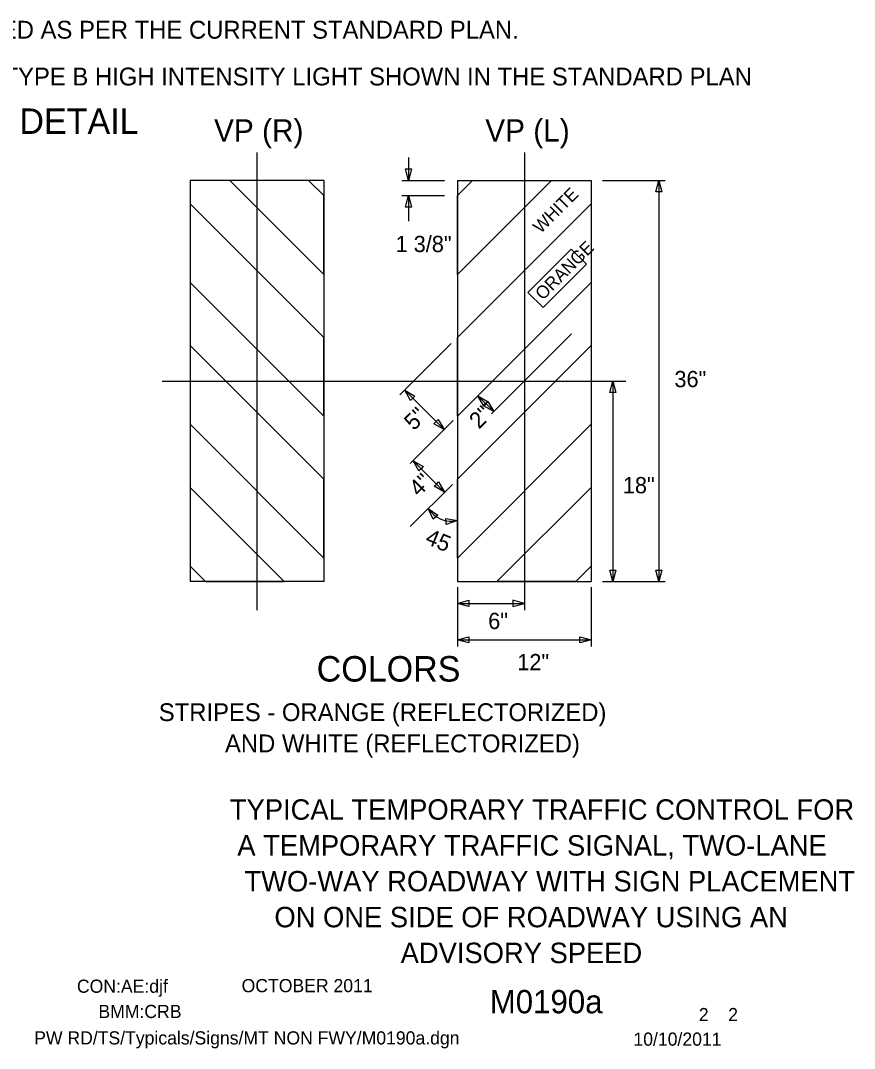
# Model space of a CAD drawing. Extents: x 16739 to 18486, y 7218 to 8208.
# Drawn here: x 18093.1 to 18486.1, y 7218.1 to 7702.3 of the extents above; entities that cross this region are included whole.
import ezdxf

# ---------------------------------------------------------------- set-up
doc = ezdxf.new("R2010")
doc.units = 0
for name, color, linetype in [('BORDER', 7, 'Continuous'), ('BORDER_SIGNAL_WO', 7, 'Continuous'), ('TRAFFIC_SIGNS_PR', 7, 'Continuous'), ('TYPICAL_TEXT_DIMEN_PR', 7, 'Continuous')]:
    doc.layers.add(name, color=color, linetype=linetype)

msp = doc.modelspace()

# ---------------------------------------------------------------- linework, layer by layer
at = {"layer": 'TRAFFIC_SIGNS_PR'}
for p, q in [((18235.99, 7627.03), (18172.99, 7627.03)), ((18172.99, 7627.03), (18172.99, 7438.03)), ((18235.99, 7582.76), (18191.73, 7627.03)), ((18235.99, 7619.89), (18228.85, 7627.03)), ((18235.99, 7627.03), (18235.99, 7438.03)), ((18299.02, 7627.03), (18362.02, 7627.03)), ((18299.02, 7627.03), (18299.02, 7438.03)), ((18299.02, 7619.89), (18306.16, 7627.03)), ((18299.02, 7582.76), (18343.29, 7627.03)), ((18362.02, 7627.03), (18362.02, 7438.03)), ((18235.99, 7553.07), (18172.99, 7616.07)), ((18299.02, 7553.07), (18362.02, 7616.07)), ((18235.99, 7515.94), (18172.99, 7578.94)), ((18299.02, 7515.94), (18362.02, 7578.94)), ((18308.3, 7562.35), (18317.58, 7571.63)), ((18235.99, 7486.25), (18172.99, 7549.25)), ((18299.02, 7486.25), (18362.02, 7549.25)), ((18235.99, 7449.12), (18172.99, 7512.12)), ((18299.02, 7449.12), (18362.02, 7512.12)), ((18217.39, 7438.03), (18172.99, 7482.42)), ((18317.63, 7438.03), (18362.02, 7482.42)), ((18180.26, 7438.03), (18172.99, 7445.3)), ((18354.75, 7438.03), (18362.02, 7445.3)), ((18235.99, 7438.03), (18172.99, 7438.03)), ((18299.02, 7438.03), (18362.02, 7438.03))]:
    msp.add_line(p, q, dxfattribs=at)
for points in [[(18228.85, 7627.03), (18191.73, 7627.03), (18235.99, 7582.76), (18235.99, 7619.89)], [(18306.16, 7627.03), (18343.29, 7627.03), (18299.02, 7582.76), (18299.02, 7619.89)], [(18235.99, 7553.07), (18172.99, 7616.07), (18172.99, 7578.94), (18235.99, 7515.94)], [(18299.02, 7553.07), (18362.02, 7616.07), (18362.02, 7578.94), (18299.02, 7515.94)], [(18235.99, 7486.25), (18172.99, 7549.25), (18172.99, 7512.12), (18235.99, 7449.12)], [(18299.02, 7486.25), (18362.02, 7549.25), (18362.02, 7512.12), (18299.02, 7449.12)], [(18172.99, 7482.42), (18172.99, 7445.3), (18180.26, 7438.03), (18217.39, 7438.03)], [(18362.02, 7482.42), (18362.02, 7445.3), (18354.75, 7438.03), (18317.63, 7438.03)]]:
    msp.add_lwpolyline(points, close=True, dxfattribs=at)
at = {"layer": 'TYPICAL_TEXT_DIMEN_PR'}
for p, q in [((18204.49, 7640.16), (18204.49, 7424.63)), ((18275.92, 7637.88), (18275.92, 7627.03)), ((18330.52, 7640.16), (18330.52, 7424.63)), ((18275.92, 7627.03), (18274.48, 7632.42)), ((18274.48, 7632.42), (18275.92, 7632.42)), ((18275.92, 7632.42), (18277.36, 7632.42)), ((18277.36, 7632.42), (18275.92, 7627.03)), ((18272.77, 7627.03), (18292.93, 7627.03)), ((18367.39, 7627.03), (18396.81, 7627.03)), ((18392.44, 7621.64), (18393.89, 7627.03)), ((18393.89, 7627.03), (18393.89, 7438.03)), ((18393.89, 7627.03), (18395.33, 7621.64)), ((18272.77, 7619.89), (18292.93, 7619.89)), ((18274.48, 7614.5), (18275.92, 7619.89)), ((18275.92, 7619.89), (18275.92, 7607.83)), ((18275.92, 7619.89), (18277.36, 7614.5)), ((18393.89, 7621.64), (18392.44, 7621.64)), ((18395.33, 7621.64), (18393.89, 7621.64)), ((18275.92, 7614.5), (18274.48, 7614.5)), ((18277.36, 7614.5), (18275.92, 7614.5)), ((18315.08, 7517.08), (18352.8, 7554.81)), ((18271.9, 7525.95), (18296.09, 7550.14)), ((18159.87, 7532.53), (18378.29, 7532.53)), ((18370.78, 7527.14), (18372.22, 7532.53)), ((18372.22, 7532.53), (18372.22, 7438.03)), ((18372.22, 7532.53), (18373.67, 7527.14)), ((18292.72, 7509.64), (18274.16, 7528.21)), ((18276.95, 7523.38), (18274.16, 7528.21)), ((18274.16, 7528.21), (18278.99, 7525.42)), ((18278.99, 7525.42), (18277.97, 7524.4)), ((18316.1, 7518.1), (18308.64, 7525.56)), ((18311.43, 7520.73), (18308.64, 7525.56)), ((18308.64, 7525.56), (18313.47, 7522.78)), ((18372.22, 7527.14), (18370.78, 7527.14)), ((18373.67, 7527.14), (18372.22, 7527.14)), ((18277.97, 7524.4), (18276.95, 7523.38)), ((18311.27, 7520.89), (18312.29, 7521.91)), ((18316.1, 7518.1), (18311.27, 7520.89)), ((18312.45, 7521.75), (18311.43, 7520.73)), ((18312.29, 7521.91), (18313.31, 7522.93)), ((18313.47, 7522.78), (18312.45, 7521.75)), ((18313.31, 7522.93), (18316.1, 7518.1)), ((18276.74, 7493.66), (18296.97, 7513.89)), ((18287.89, 7512.43), (18288.91, 7513.45)), ((18292.72, 7509.64), (18287.89, 7512.43)), ((18288.91, 7513.45), (18289.93, 7514.47)), ((18289.93, 7514.47), (18292.72, 7509.64)), ((18292.92, 7480.15), (18278.07, 7494.99)), ((18280.86, 7490.16), (18278.07, 7494.99)), ((18278.07, 7494.99), (18282.9, 7492.2)), ((18282.9, 7492.2), (18281.88, 7491.19)), ((18281.88, 7491.19), (18280.86, 7490.16)), ((18276.74, 7463.97), (18296.62, 7483.85)), ((18288.09, 7482.93), (18289.11, 7483.95)), ((18292.92, 7480.15), (18288.09, 7482.93)), ((18289.11, 7483.95), (18290.13, 7484.98)), ((18290.13, 7484.98), (18292.92, 7480.15)), ((18287.62, 7467.42), (18285.23, 7472.45)), ((18285.23, 7472.45), (18289.82, 7469.29)), ((18288.72, 7468.35), (18287.62, 7467.42)), ((18289.82, 7469.29), (18288.72, 7468.35)), ((18293.65, 7466.39), (18293.55, 7467.83)), ((18293.55, 7467.83), (18299.02, 7466.74)), ((18293.74, 7464.95), (18293.65, 7466.39)), ((18299.02, 7466.74), (18293.74, 7464.95)), ((18372.22, 7438.03), (18370.78, 7443.42)), ((18370.78, 7443.42), (18372.22, 7443.42)), ((18372.22, 7443.42), (18373.67, 7443.42)), ((18373.67, 7443.42), (18372.22, 7438.03)), ((18393.89, 7438.03), (18392.44, 7443.42)), ((18392.44, 7443.42), (18393.89, 7443.42)), ((18393.89, 7443.42), (18395.33, 7443.42)), ((18395.33, 7443.42), (18393.89, 7438.03)), ((18299.02, 7435.41), (18299.02, 7407.43)), ((18362.02, 7435.41), (18362.02, 7407.43)), ((18367.39, 7438.03), (18396.81, 7438.03)), ((18299.02, 7427.77), (18304.41, 7429.22)), ((18304.41, 7429.22), (18304.41, 7427.77)), ((18330.52, 7427.77), (18325.13, 7429.22)), ((18325.13, 7429.22), (18325.13, 7427.77)), ((18299.02, 7427.77), (18330.52, 7427.77)), ((18304.41, 7426.33), (18299.02, 7427.77)), ((18304.41, 7427.77), (18304.41, 7426.33)), ((18325.13, 7427.77), (18325.13, 7426.33)), ((18325.13, 7426.33), (18330.52, 7427.77)), ((18299.02, 7410.62), (18304.41, 7412.06)), ((18299.02, 7410.62), (18362.02, 7410.62)), ((18304.41, 7409.17), (18299.02, 7410.62)), ((18304.41, 7412.06), (18304.41, 7410.62)), ((18304.41, 7410.62), (18304.41, 7409.17)), ((18356.63, 7410.62), (18356.63, 7412.06)), ((18356.63, 7412.06), (18362.02, 7410.62)), ((18362.02, 7410.62), (18356.63, 7409.17)), ((18356.63, 7409.17), (18356.63, 7410.62))]:
    msp.add_line(p, q, dxfattribs=at)
msp.add_lwpolyline([(18332.19, 7574.28), (18352.61, 7594.71), (18359.79, 7587.52), (18339.37, 7567.1)], close=True, dxfattribs=at)
msp.add_arc((18296.26, 7479.57), 13.12, 212.8393, 282.1565, dxfattribs=at)

# ---------------------------------------------------------------- texts
at = {"layer": 'BORDER'}
for s, p in [('TYPICAL TEMPORARY TRAFFIC CONTROL FOR', (18191.75, 7325.83)), ('A TEMPORARY TRAFFIC SIGNAL, TWO-LANE', (18195.27, 7308.94)), ('TWO-WAY ROADWAY WITH SIGN PLACEMENT', (18198.63, 7292.06)), ('ON ONE SIDE OF ROADWAY USING AN', (18212.75, 7275.17)), ('ADVISORY SPEED', (18272.23, 7258.28))]:
    msp.add_text(s, height=9.6347, dxfattribs=at).set_placement(p)
at = {"layer": 'BORDER_SIGNAL_WO'}
for s, height, p in [('CON:AE:djf', 6.2, (18119.69, 7244.31)), ('    OCTOBER 2011    ', 6.2, (18188.08, 7244.59)), ('    M0190a    ', 11, (18297.86, 7234.63)), ('BMM:CRB   ', 6.2, (18129.81, 7232.42)), (' 2    2 ', 6.2, (18410.45, 7230.95)), ('PW RD/TS/Typicals/Signs/MT NON FWY/M0190a.dgn     ', 6.2, (18099.55, 7219.96)), ('10/10/2011    ', 6.2, (18381.93, 7219.38))]:
    msp.add_text(s, height=height, dxfattribs=at).set_placement(p)
at = {"layer": 'TYPICAL_TEXT_DIMEN_PR'}
for s, height, p in [('TEMPORARY CONCRETE BARRIER SHALL BE APPLIED AS PER THE CURRENT STANDARD PLAN.', 8.4, (17801.7, 7693.82)), ('VERTICAL PANELS SHALL BE USED IN LIEU OF THE TYPE B HIGH INTENSITY LIGHT SHOWN IN THE STANDARD PLAN ', 8.4, (17801.7, 7671.77)), ('SIGN DETAIL', 12, (18048.89, 7648.94)), ('VP (R)', 10.5, (18184.3, 7645.33)), ('VP (L)', 10.5, (18312.1, 7645.33)), ('1 3/8"', 7.654, (18269.84, 7593.26)), ('36"', 7.654, (18401.23, 7529.62)), ('18"', 7.654, (18376.93, 7479.63)), ('6"', 7.654, (18313.48, 7415.67)), ('COLORS', 12, (18232.64, 7390.93)), ('12"', 7.654, (18327.19, 7396.27)), ('STRIPES - ORANGE (REFLECTORIZED)', 8.4, (18158.25, 7372.3)), ('          AND WHITE (REFLECTORIZED)', 8.4, (18158.25, 7357.6))]:
    msp.add_text(s, height=height, dxfattribs=at).set_placement(p)
for s, height, rotation, p in [('WHITE', 6, 45, (18338.21, 7601.7)), ('ORANGE', 6, 45, (18339.24, 7570.26)), ('5"', 7.654, 45, (18278.49, 7508.84)), ('2"', 7.654, 45.0095, (18309.18, 7509.58)), ('4"', 7.654, 45, (18280.84, 7477.73)), ('45', 7.655, 337.5007, (18283.31, 7456.13))]:
    msp.add_text(s, height=height, rotation=rotation, dxfattribs=at).set_placement(p)

doc.saveas('drawing.dxf')
